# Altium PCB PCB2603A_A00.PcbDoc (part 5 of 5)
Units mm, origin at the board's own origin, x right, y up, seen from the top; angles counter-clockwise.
Board outline 35.56 x 55.88 mm, 8 copper layers (Top Layer, Signal Layer 1, Signal Layer 2, Signal Layer 3, Signal Layer 4, Signal Layer 5, Signal Layer 6, Bottom Layer), stack 1.497 mm thick; 167 components, 113 nets, 4957 pads, 645 vias.
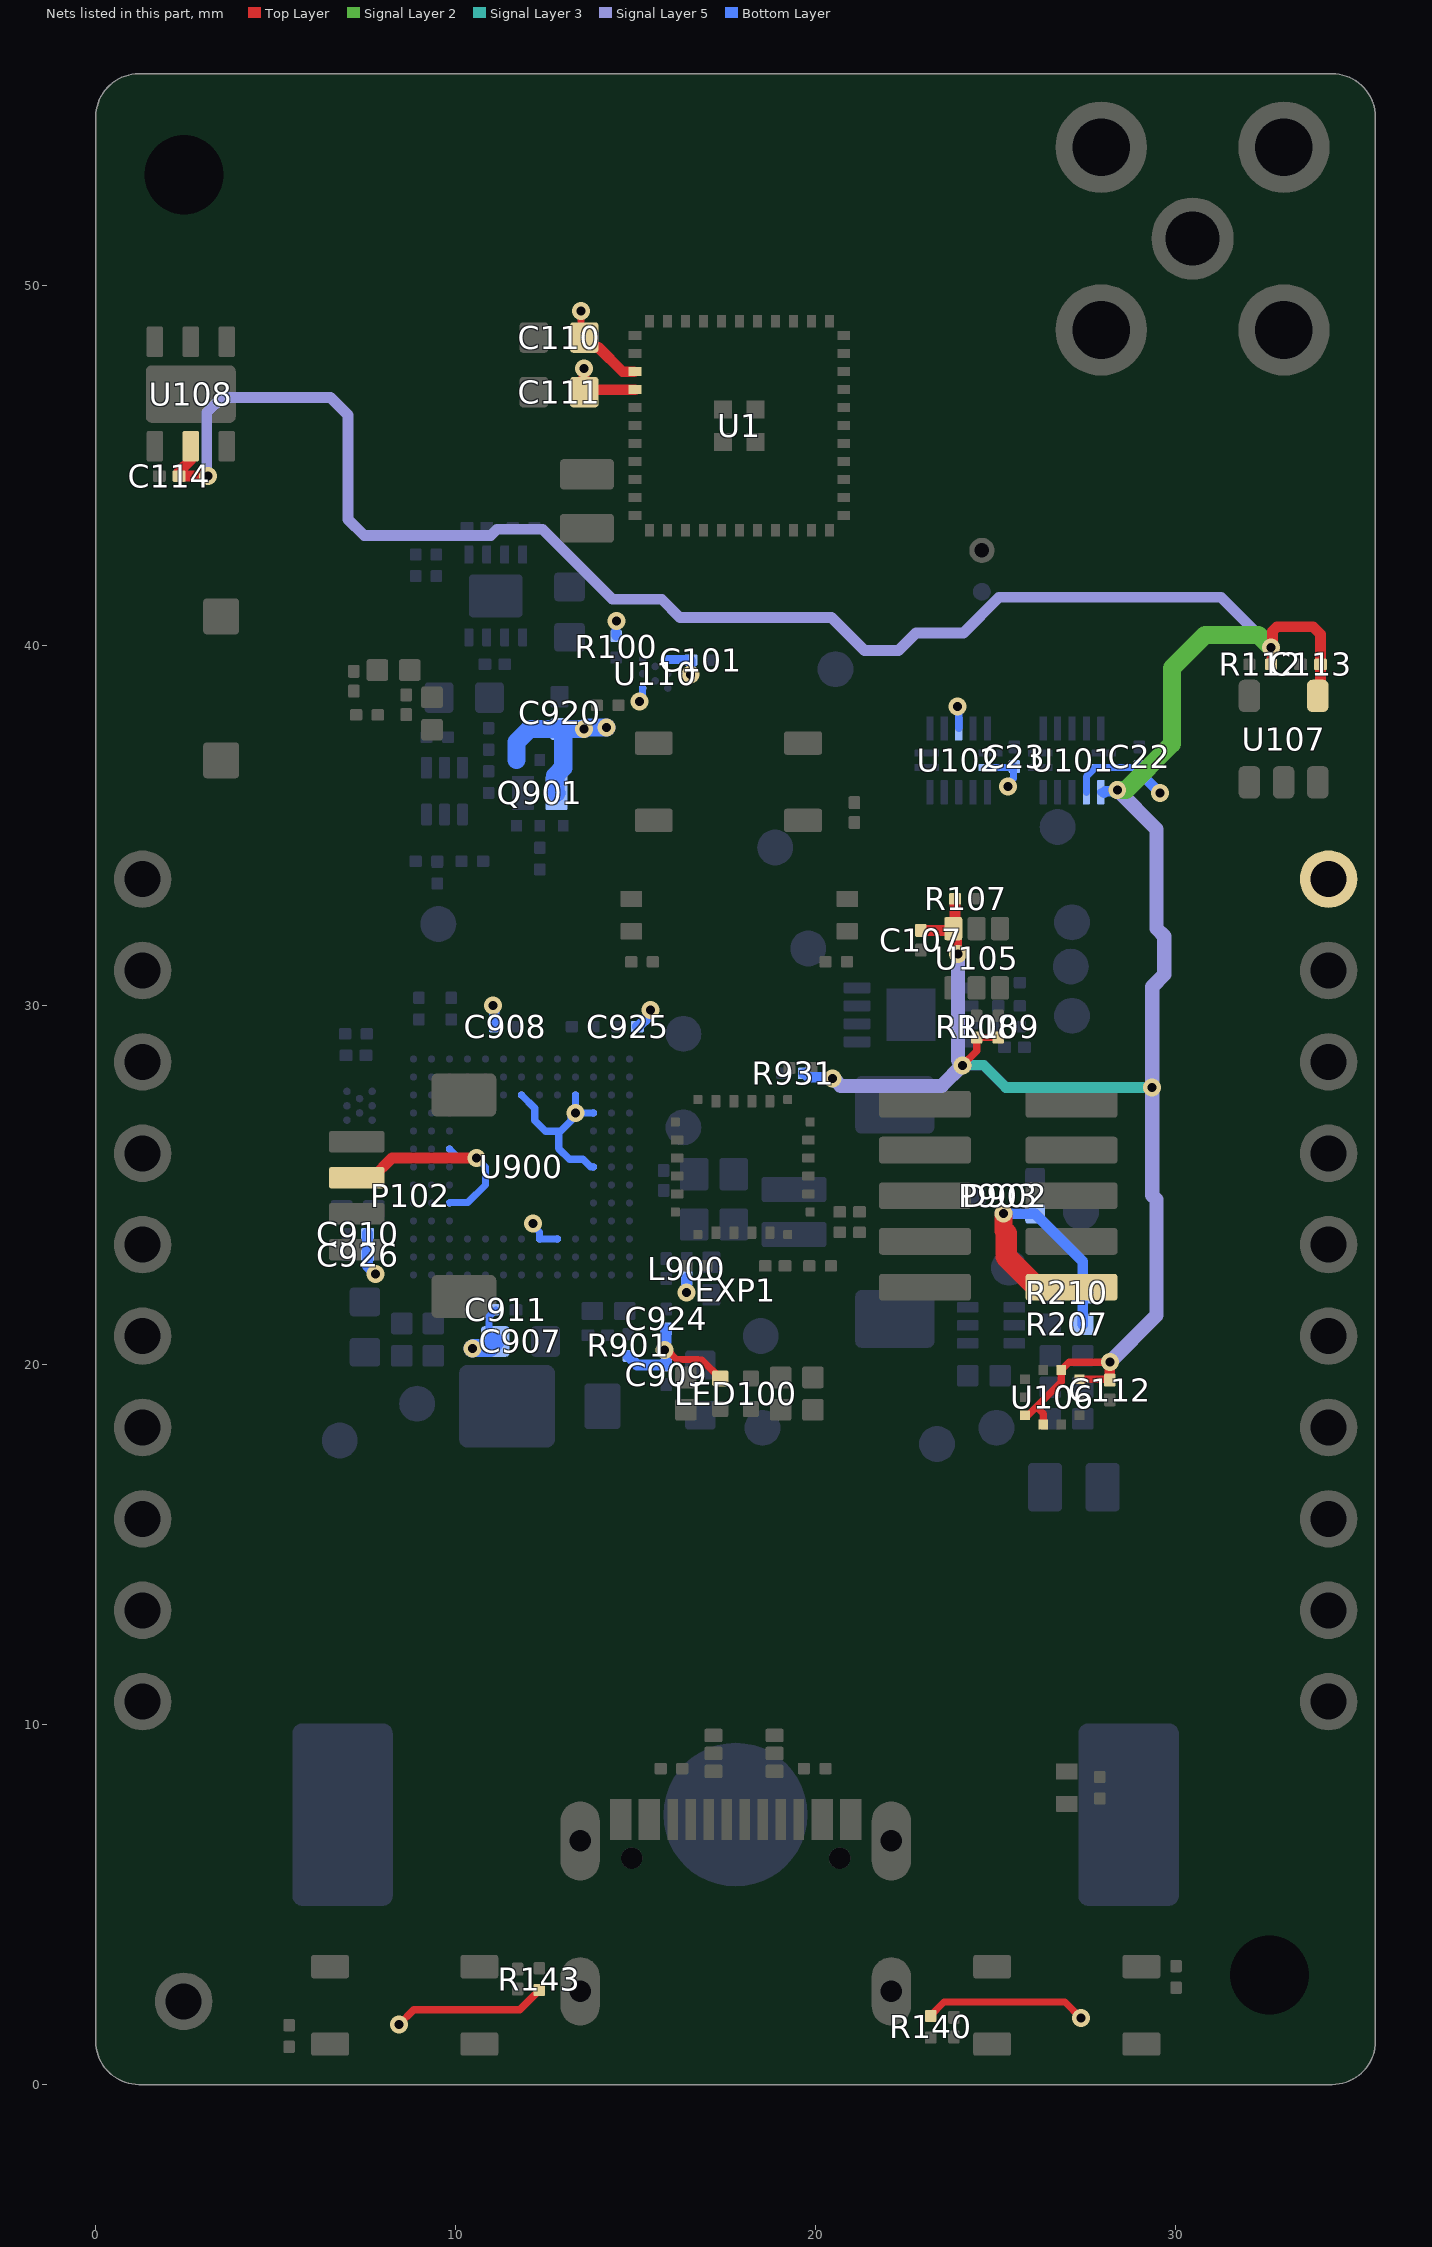
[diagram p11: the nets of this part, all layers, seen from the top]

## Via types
v1: diameter 0.5, hole 0.25, Top Layer to Bottom Layer, tented both sides, 645 vias

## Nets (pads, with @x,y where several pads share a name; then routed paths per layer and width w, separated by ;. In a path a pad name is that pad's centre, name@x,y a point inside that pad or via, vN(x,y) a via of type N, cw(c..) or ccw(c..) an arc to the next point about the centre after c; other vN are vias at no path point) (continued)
VDD_SENSOR: C107.1 C112.1 C113.1 C114.1 R107.1 R108.1 R109.1 R112.1 R931.2 U101.1 U105.6 U106.1 U106.5 U106.6 U106.10 U107.4 U108.5 | length 90.8
  Top Layer w0.2: v1(24.08,28.325) 24.48,28.725 R108.1@24.48,29.1 R109.1@25.08,29.1 ; U106.5@25.823,18.6 25.905,18.6 26.143,18.838 ; U106.6@26.33,18.343 26.33,18.65 26.143,18.838 ; U106.10@27.337,19.6 28.155,19.6 C112.1@28.18,19.575 ; v1(28.18,20.075) 27.048,20.075 U106.1@26.83,19.858 26.83,19.525 26.143,18.838 ; R112.1@32.66,39.465 32.641,39.484 32.641,39.816 32.665,39.839 v1(32.665,39.937)
  Top Layer w0.3: U108.5@2.64,45.3 2.64,45.15 2.315,44.825 C114.1@2.315,44.7 2.318,44.703 2.945,44.703 2.997,44.755 v1@3.051,44.755 ; C107.1@22.93,32.075 23.78,32.075 U105.6@23.83,32.125 ; R107.1@23.88,32.95 23.88,32.175 U105.6@23.83,32.125 ; v1(23.963,31.418) 23.925,31.456 23.925,32.03 U105.6@23.83,32.125 ; C112.1@28.18,19.575 v1(28.18,20.075) ; v1(32.665,39.937) 32.703,39.975 32.703,40.386 32.83,40.512 33.825,40.512 34.035,40.303 C113.1@34.035,39.465 ; U107.4@33.96,38.59 34.035,38.665 C113.1@34.035,39.44
  Signal Layer 2 w0.5: v1(28.387,35.98) 28.625,35.98 29.906,37.261 29.906,39.369 30.825,40.288 32.314,40.288 v1(32.665,39.937)
  Signal Layer 5 w0.3: v1@3.082,44.786 3.082,46.464 3.505,46.887 6.523,46.887 7.011,46.398 7.011,43.495 7.459,43.048 10.978,43.048 11.152,43.221 12.413,43.221 14.359,41.275 15.727,41.275 16.232,40.77 20.449,40.77 21.367,39.852 22.308,39.852 22.797,40.341 24.114,40.341 25.103,41.33 31.272,41.33 v1(32.665,39.937)
  Signal Layer 5 w0.4: v1@20.499,27.933 20.526,27.933 20.708,27.75 23.505,27.75 v1(24.08,28.325) 24.08,28.352 23.963,28.469 v1(23.963,31.418) ; v1(28.18,20.075) 29.479,21.374 29.479,24.594 29.357,24.717 v1(29.357,27.712) 29.357,30.51 29.696,30.849 29.696,31.911 29.479,32.128 29.479,34.888 v1(28.387,35.98)
  Signal Layer 3 w0.3: v1(24.08,28.325) 24.677,28.325 25.289,27.712 v1(29.357,27.712)
  Bottom Layer w0.2: U101.1@27.93,35.915 28.009,35.915 U101.1@28.017,35.907 ; v1@28.294,35.915 28.321,35.942 28.359,35.98 v1(28.387,35.98)
  Bottom Layer w0.3: R931.2@19.68,28.1 19.69,28.09 19.7,28.09 19.8,27.99 20.441,27.99 v1(20.479,27.952) ; U101.1@28.017,35.907 28.052,35.942 28.321,35.942 28.349,35.942 v1(28.387,35.98)
  other v1: 3.12,44.7
VMCU: C22.1 C23.1 C101.1 C110.1 C111.1 C907.1 C908.1 C909.1 C910.1 C911.1 C920.1 C924.1 C925.1 C926.1 D902.2 EXP1.2 L900.1 LED100.1 P102.2 P903.1 Q901.4 Q901.6 Q901.7 R100.2 R140.1 R143.1 R207.2 R210.2 R901.2 U1.25 U1.26 U101.2 U101.14 U102.10 U102.14 U110.A1 U110.E3 U900.C6 U900.C9 U900.G3 U900.H11 U900.J11 U900.K3 U900.L4 U900.L7 | length 54.6
  Top Layer w0.2: v1(8.429,1.669) 8.838,2.078 11.783,2.078 12.325,2.62 R143.1@12.325,2.63 ; C110.1@13.486,48.47 v1(13.486,49.288) ; v1(15.801,20.41) 15.882,20.41 16.141,20.15 16.748,20.15 16.767,20.131 16.849,20.131 LED100.1@17.355,19.625 ; R140.1@23.2,1.904 23.2,1.914 23.576,2.29 26.936,2.29 v1(27.376,1.85) ; v1@23.859,38.262 23.895,38.297 v1(23.952,38.297)
  Top Layer w0.25: v1(16.526,39.189) v1@16.526,39.195
  Top Layer w0.3: P102.2@7.255,25.2 7.68,25.2 8.23,25.75 v1(10.58,25.75) ; v1(13.566,47.684) 13.571,47.679 13.571,47.17 C111.1@13.641,47.1 ; C111.1@13.575,47.032 13.643,47.1 U1.26@14.985,47.1 ; C110.1@13.575,48.55 13.575,48.525 13.825,48.275 13.97,48.275 14.645,47.6 U1.25@14.96,47.6
  Top Layer w0.5: v1(25.23,24.2) 25.23,23.725 25.305,23.65
  Top Layer w0.6: 25.305,23.65 25.305,23 26.075,22.23 27.045,22.23 P903.1@27.115,22.16
  Signal Layer 5 w0.4: v1@10.58,25.723 v1(10.58,25.75) v1@10.607,25.75 ; v1@12.136,23.906 v1(12.155,23.925) v1@12.155,23.898 ; v1@13.311,27.019 v1(13.33,27)
  Bottom Layer w0.2: U900.C9@9.83,24.5 9.84,24.51 10.34,24.51 10.83,25 10.83,25.5 v1(10.58,25.75) 10.08,25.75 U900.C6@9.83,26 ; C907.1@10.925,20.655 10.925,21.345 11.105,21.525 C911.1@11.125,21.525 ; U900.G3@11.83,27.5 12.197,27.133 12.197,26.79 12.495,26.492 12.915,26.492 ; v1(12.155,23.925) 12.155,23.87 12.33,23.695 U900.H11@12.33,23.5 U900.J11@12.83,23.5 ; U900.K3@13.33,27.5 v1(13.33,27) ; U900.L7@13.83,25.5 13.755,25.5 13.544,25.712 13.164,25.712 12.867,26.009 12.867,26.443 12.915,26.492 ; U900.L4@13.83,27 v1(13.33,27) ; v1(15.106,38.442) 15.195,38.53 15.195,38.806 U110.E3@15.197,38.808 ; v1(23.952,38.297) 23.98,38.27 U102.10@23.98,37.685 ; U102.14@24.865,36.6 C23.1@25.505,36.6 ; v1(25.355,36.074) 25.355,36.155 25.505,36.305 C23.1@25.505,36.6 ; C23.1@25.53,36.625 C23.1@25.505,36.6 ; U101.2@27.53,35.915 27.53,36.355 27.775,36.6 28.975,36.6 C22.1@29,36.625 ; 12.915,26.492 13.213,26.79 13.213,26.883 v1(13.33,27)
  Bottom Layer w0.25: R100.2@14.46,40.255 14.46,40.671 v1(14.466,40.677) ; U110.A1@15.897,39.608 16.524,39.608 C101.1@16.544,39.588 16.542,39.587 16.542,39.206 v1(16.526,39.189)
  Bottom Layer w0.3: C910.1@7.555,23.65 C926.1@7.555,23.05 7.555,22.75 v1(7.78,22.525) ; v1(11.044,29.983) 11.075,29.952 11.075,29.41 11.085,29.4 C908.1@11.105,29.4 ; R901.2@14.8,20.25 14.8,20.24 15.04,20 C909.1@15.855,20 15.855,20.33 15.801,20.384 v1(15.801,20.41) 15.839,20.448 15.839,20.63 15.845,20.636 15.845,20.99 C924.1@15.855,21 ; C925.1@15.055,29.4 15.075,29.4 15.374,29.699 15.374,29.823 v1(15.412,29.861) ; v1(16.421,22.012) 16.426,22.016 16.426,22.401 L900.1@16.43,22.405 ; v1(25.23,24.2) D902.2@26.105,24.2 27.43,22.875 R210.2@27.43,22 27.43,21.95 R207.2@27.43,21.125 ; C22.1@29,36.625 29.01,36.615 29.01,36.457 v1(29.58,35.887)
  Bottom Layer w0.5: v1(10.474,20.458) 10.491,20.475 10.95,20.475 11.1,20.625 C907.1@11.1,20.65 ; v1(13.565,37.67) 13.603,37.708 v1(14.193,37.708)
  Bottom Layer w0.508: Q901.4@11.69,36.808 11.69,37.313 12.047,37.67 C920.1@12.89,37.67 v1(13.565,37.67) ; Q901.7@12.806,35.895 12.765,35.936 12.765,36.37 12.99,36.595 Q901.6@12.99,36.808 12.99,37.528 C920.1@12.89,37.628
pads on no net: c.7 c.9 LOGO_SEGGER.1 M901.1 M902.1 P102.5 P102.6 P900.1 P900.2 P900.A8 P900.B8 U1.18 U1.24 U104.1 U104.2 U104.3 U104.4 U104.5 U104.6 U104.7 U104.14 U104.15 U104.16 U104.17 U104.19 U104.20 U104.21 U105.4 U108.3 U108.4 U108.7 U110.C1 U900.B4 U900.B5 U900.B6 U900.B7 U900.B8 U900.B9 U900.B11 U900.C4 U900.C7 U900.D2 U900.D13 U900.E2 U900.E11 U900.E12 U900.E13 U900.F1 U900.F2 U900.F3 U900.F11 U900.F12 U900.G1 U900.G2 U900.G12 U900.H1 U900.H2 U900.J1 U900.J2 U900.K1 U900.K2 U900.K13 U900.L3 U900.L11 U900.L12 U900.L13 U900.M2 U900.M3 U900.M4 U900.M5 U900.M6 U900.M12 U900.M13 U900.N3 U900.N4 U900.N5 U900.N6 U900.N7 U900.N13 U901.C1 U902.8 U903.9
copper on no net:
  other v1: 31.289,4.77

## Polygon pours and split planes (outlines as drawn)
GND on Signal Layer 1 "GND_L02" (solid, remove dead copper, pour order 1): -0.015,0 -0.015,55.88 35.56,55.88 35.56,0
GND on Signal Layer 4 "GND_L05" (solid, remove dead copper, pour order 11): -0.015,0 -0.015,55.88 35.56,55.88 35.56,0
GND on Signal Layer 5 "GND_L06" (solid, remove dead copper, pour order 7): -0.015,0 -0.015,55.88 35.56,55.88 35.56,0
GND on Signal Layer 2 "GND_L03" (solid, remove dead copper, pour order 10): -0.015,0 -0.015,55.88 35.56,55.88 35.56,0
GND on Signal Layer 3 "GND_L04" (solid, remove dead copper, pour order 6): -0.015,0 -0.015,55.88 35.56,55.88 35.56,0
GND on Bottom Layer "GND_L08" (solid, remove dead copper, pour order 8): -0.015,0 -0.015,55.88 35.56,55.88 35.56,0
GND on Top Layer "CC" (solid, remove dead copper, pour order 0): -0.015,0 -0.015,55.88 35.56,55.88 35.56,0
VMCU on Signal Layer 6 "VMCU_L07" (solid, remove dead copper, pour order 9): -0.015,0 -0.015,55.88 35.56,55.88 35.56,0

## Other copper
Top Layer:
  pour cut-out: 20.177,26.014 20.197,26.034 20.657,26.034 20.657,25.867 20.517,25.727 20.457,25.787 20.184,25.787
  pour cut-out: 21.807,25.593 21.807,25.085 21.82,25.073 24.153,25.073 24.217,25.137 24.217,25.548 24.185,25.58
  pour cut-out: 12.233,42.705 15.166,42.705 15.166,44.801 14.723,45.245 12.257,45.245
  pour cut-out: 25.919,26.301 25.919,25.669 25.944,25.645 25.944,25.186 28.335,25.186 28.335,26.202 28.193,26.344
  pour cut-out: 6.598,35.403 6.598,42.431 0.153,42.431 0.153,35.403
Signal Layer 2:
  pour cut-out: 5.477,21.481 5.778,21.481 5.778,21.48 5.778,21.646 5.727,21.698 5.487,21.698 5.484,21.695
  pour cut-out: 16.076,49.381 16.164,49.469 17.817,49.469 17.817,50.075 17.77,50.123 16.054,50.123 16.043,50.112 16.091,50.064 16.091,49.414
  pour cut-out: 14.637,36.387 14.669,36.355 15.338,36.355 15.338,37.666 15.295,37.709 14.664,37.709
Bottom Layer:
  pour cut-out: 17.193,19.118 17.193,19.489 17.197,19.493 16.788,19.493 16.724,19.429 16.724,19.11
  region net N16784657: 8.357,4.811 8.357,11.509 5.295,11.509 5.295,4.811
  pour cut-out: 25.451,24.894 25.451,24.518 25.447,24.513 25.626,24.513 25.626,24.85 25.657,24.881
  pour cut-out: 25.5,20.027 25.5,19.68 25.563,19.617 25.709,19.617 25.757,19.666 25.743,19.68 25.743,20.013
  pour cut-out: 12.44,39.27 12.665,39.27 12.665,38.77 12.44,38.77
  pour cut-out: 8.364,22.1 15.28,22.1 15.28,29.114 8.415,29.114
  pour cut-out: 6.98,20.95 6.98,21.85 7.93,21.85 7.93,20.95
Multi-Layer:
  pour cut-out: -0.119,43.751 -0.119,50.001 cw(c0.381,50.001) 0.381,50.501 4.881,50.501 cw(c4.881,50.001) 5.381,50.001 5.381,43.751 cw(c4.881,43.751) 4.881,43.251 0.381,43.251 cw(c0.381,43.751)

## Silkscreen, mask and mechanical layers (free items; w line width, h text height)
Top Solder:
  lines w0.8: -2.398,4.25 -2.398,1.189 ccw(c1.191,1.189) 1.191,-2.4 34.371,-2.4 ccw(c34.371,1.189) 37.96,1.189 37.96,4.25 ; -2.398,51.63 -2.398,54.795 cw(c1.139,54.743) 1.191,58.28 34.474,58.28 ; -2.397,4.25 -2.398,12.25 ; -2.398,16.75 -2.398,47.13 ; 0,54.808 0,1.19 ccw(c1.19,1.191) 1.191,0.001 ; 0,54.81 cw(c1.072,54.808) 1.074,55.88 ; 1.072,55.88 34.47,55.88 ; 1.191,0 34.369,0 ; 34.371,0 ccw(c34.371,1.189) 35.56,1.19 35.56,54.79 ; 34.374,58.262 cw(c34.474,54.778) 37.957,54.878 ; 34.468,55.88 cw(c34.47,54.79) 35.56,54.792 ; 37.959,54.778 37.959,51.63 37.96,51.63 ; 37.96,12.25 37.961,4.25 ; 37.96,16.75 37.96,47.13 ; 0,1.2 ccw(c1.2,1.2) 1.2,0 ; 0,1.2 ccw(c1.2,1.2) 1.2,0 ; 0,1.2 0,54.68 ; 0,1.2 0,54.68 ; 0,54.68 cw(c1.2,54.68) 1.2,55.88 ; 0,54.68 cw(c1.2,54.68) 1.2,55.88 ; 1.2,0 34.36,0 ; 1.2,0 34.36,0 ; 1.2,55.88 34.36,55.88 ; 1.2,55.88 34.36,55.88 ; 34.36,0 ccw(c34.36,1.2) 35.56,1.2 cw(c34.36,1.2) 34.36,0 ; 34.36,55.88 cw(c34.36,54.68) 35.56,54.68 ccw(c34.36,54.68) 34.36,55.88 ; 35.561,1.2 35.561,54.68 35.561,1.2
Bottom Solder:
  lines w0.8: -2.398,1.189 ccw(c1.191,1.189) 1.191,-2.4 ; -2.398,16.75 -2.398,47.13 ; -2.398,51.63 -2.397,51.63 -2.397,54.709 ; -2.398,54.795 cw(c1.139,54.743) 1.191,58.28 ; -2.398,1.189 -2.398,4.25 -2.398,12.25 ; 0,44.4 0,1.189 ccw(c1.19,1.19) 1.191,0 ; 0.001,54.807 0.001,1.19 ccw(c1.191,1.191) 1.192,0.001 ; 0.001,54.808 cw(c1.074,54.807) 1.076,55.88 ; 1.074,55.88 34.469,55.88 ; 1.192,-2.4 34.372,-2.4 ; 1.192,0 34.37,0 ; 1.192,58.28 34.371,58.28 cw(c34.471,54.791) 37.96,54.891 ; 34.371,-2.4 ccw(c34.371,1.189) 37.96,1.189 ; 34.371,0 ccw(c34.371,1.189) 35.56,1.189 35.56,44.4 ; 34.372,0 ccw(c34.372,1.189) 35.561,1.19 35.561,54.788 ; 34.467,55.88 cw(c34.469,54.788) 35.561,54.79 ; 37.96,12.25 37.961,4.25 37.961,1.189 ; 37.96,16.75 37.96,47.13 ; 37.96,51.63 37.96,54.984 ; 0,1.2 ccw(c1.2,1.2) 1.2,0 ; 0,1.2 ccw(c1.2,1.2) 1.2,0 ; 0,1.2 0,54.68 ; 0,1.2 0,54.68 ; 0,54.68 cw(c1.2,54.68) 1.2,55.88 ; 0,54.68 cw(c1.2,54.68) 1.2,55.88 ; 1.2,0 34.36,0 ; 1.2,0 34.36,0 ; 1.2,55.88 34.36,55.88 ; 1.2,55.88 34.36,55.88 ; 34.36,0 ccw(c34.36,1.2) 35.56,1.2 cw(c34.36,1.2) 34.36,0 ; 34.36,55.88 cw(c34.36,54.68) 35.56,54.68 ccw(c34.36,54.68) 34.36,55.88 ; 35.561,1.2 35.561,54.68 35.561,1.2
BOARD OUTLINE 1:
  drawing of 315 lines, arcs and shapes, not listed
  text "Milling 0.8 mm (2 pcs)" at 6.177,42.873 h0.9 r90
Mechanical 15:
  lines w0.1: 2.08,0 3.08,0 ; 2.58,-0.5 2.58,0.5
Top EXT_SILKP 21/EXT_SILKS 22:
  text "ZGM230S" at 13.818,40.388 h2
  text "RESET" at 15.745,38.164 h1.27
  text "2" at 31.94,33.06 h1.5
  text "1" at 3.083,33 h1.5
  text "LED1" at 11.479,32.092 h1.27
  text "LED0" at 17.328,32.099 h1.27
  text "4" at 31.94,30.512 h1.5
  text "3" at 3.083,30.42 h1.5
  text "6" at 31.94,27.972 h1.5
  text "5" at 3.083,27.845 h1.5
  text "8" at 31.94,25.435 h1.5
  text "7" at 3.083,25.295 h1.5
  text "10" at 31.385,22.935 h1.5
  text "9" at 3.083,22.82 h1.5
  text "2" at 22.54,20.792 h1.27
  text "1" at 26.73,20.792 h1.27
  text "12" at 31.385,20.41 h1.5
  text "RGB LED" at 15.364,20.294 h1.27
  text "11" at 2.808,20.22 h1.5
  text "14" at 31.385,17.835 h1.5
  text "13" at 2.783,17.645 h1.5
  text "16" at 31.385,15.31 h1.5
  text "15" at 2.783,15.145 h1.5
  text "18" at 31.385,12.76 h1.5
  text "17" at 2.783,12.595 h1.5
  text "20" at 31.385,10.26 h1.5
  text "19" at 2.783,10.095 h1.5
  text "BTN0" at 25.603,3.849 h1.27
  text "BTN1" at 7.281,3.842 h1.27
Bottom EXT_SILKP 21/EXT_SILKS 22:
  circle w0.152: c2.443,2.313 r0.966
  lines w0.152: 13.34,52.055 13.34,51.055 14.34,51.055 ; 13.34,54.105 13.34,55.105 14.34,55.105 ; 22.84,51.055 23.84,51.055 23.84,52.055 ; 22.84,55.105 23.84,55.105 23.84,54.105
  text "PCB2603A Rev A00" at 34.093,34.87 h1.5 r270
Mechanical 26:
  lines w0.2: -117.029,-49.807 -112.029,-49.807 ; -117.029,-2.807 -112.029,-2.807 ; -117.017,44.193 -112.029,44.193 ; -45.821,-96.838 -45.821,-91.838 ; -45.821,88.162 -45.821,93.162 ; 25.479,-96.838 25.479,-91.838 ; 25.479,88.162 25.479,93.162 ; 96.679,-96.838 96.679,-91.838 ; 96.679,88.162 96.679,93.162 ; 162.971,-49.807 167.971,-49.807 ; 162.971,-2.807 167.971,-2.807 ; 162.971,44.193 167.959,44.193 ; -117.017,-96.838 -117.017,93.154 167.971,93.154 167.971,-96.838 -117.017,-96.838 ; -112.029,-91.838 -112.029,88.162 162.971,88.162 162.971,-91.838 -112.029,-91.838
  text "1" at -84.129,89.733 h1.52
  text "2" at -11.821,89.733 h1.52
  text "3" at 60.779,89.733 h1.52
  text "4" at 131.579,89.733 h1.52
  text "D" at 164.969,70.593 h1.52
  text "D" at -115.142,69.388 h1.52
  text "C" at -115.142,21.893 h1.52
  text "C" at 164.842,21.893 h1.52
  text "B" at -115.142,-25.707 h1.52
  text "B" at 164.842,-25.707 h1.52
  text "A" at -115.142,-73.207 h1.52
  text "A" at 164.842,-73.207 h1.52
  text "1" at -82.909,-95.28 h1.52
  text "2" at -11.821,-95.28 h1.52
  text "3" at 60.479,-95.28 h1.52
  text "4" at 131.179,-95.28 h1.52
Mechanical 27:
  circle w0.152: c78.907,-70.307 r0.762
  circle w0.152: c78.907,-70.307 r1.778
  circle w0.254: c46.923,-84.764 r2.962
  lines w0.152: 67.909,-70.307 75.275,-70.307 ; 76.621,-70.307 81.193,-70.307 ; 68.671,-71.069 74.488,-72.085 74.513,-68.529 68.671,-69.545 68.671,-71.069
  lines w0.2: 42.874,-91.698 42.874,-64.838 82.888,-64.838 ; 42.874,-77.474 162.839,-77.474 ; 42.888,-73.838 82.888,-73.838 ; 63.169,-91.647 63.169,-77.55 ; 63.169,-73.791 63.169,-64.875 ; 142.888,-77.448 142.888,-73.838 ; 152.888,-73.838 152.888,-64.838 ; 162.888,-73.838 82.888,-73.838 ; 162.888,-64.838 82.888,-64.838 ; 82.888,-73.838 82.888,-64.838
  text "SIZE" at 44.888,-66.838 h1.52
  text "DOC NO" at 84.888,-66.838 h1.52
  text "REV" at 154.888,-66.838 h1.52
  text "PROJECTION" at 64.185,-67.187 h1.52
  text "A00" at 154.609,-71.759 h2.54
  text "BRD2603A" at 85.21,-72.2 h2.54
  text "A4" at 47.538,-72.212 h2.54
  text "REF" at 44.888,-75.838 h1.52
  text "SHEET" at 143.888,-75.838 h1.52
  text "1 of 2" at 153.73,-76.875 h1.52
  text "This drawing is confidential and is supplied on the express" at 63.652,-80.446 h1.52
  text "condition that it shall not be loaned, copied or disclosed to any" at 63.652,-82.986 h1.52
  text "other person or used for any purpose without the written consent of" at 63.652,-85.526 h1.52
  text "C" at 46.329,-85.78 h2.03
  text "2021" at 51.409,-85.932 h2.54
  text "SILICON LABS" at 64.083,-89.818 h2.54
Mechanical 28:
  lines w0.2: -117.029,-49.807 -112.029,-49.807 ; -117.029,-2.807 -112.029,-2.807 ; -117.017,44.193 -112.029,44.193 ; 162.971,-49.807 167.971,-49.807 ; 162.971,-2.807 167.971,-2.807 ; 162.971,44.193 167.971,44.193
  lines w0.203: -112.054,-91.838 -112.054,88.162 ; -112.029,-91.838 162.971,-91.838 162.971,88.162 -112.029,88.162 ; -45.821,-96.838 -45.821,-91.838 ; -45.821,88.162 -45.821,93.162 ; 25.479,-96.838 25.479,-91.838 ; 25.479,88.162 25.479,93.162 ; 96.679,-96.838 96.679,-91.838 ; 96.679,88.162 96.679,93.162 ; -117.017,-96.838 167.971,-96.838 167.971,93.154 -117.017,93.154 -117.017,-96.838
  text "4" at -83.113,89.733 h1.52
  text "3" at -10.805,89.733 h1.52
  text "2" at 61.795,89.733 h1.52
  text "1" at 132.595,89.733 h1.52
  text "D" at 165.985,70.593 h1.52
  text "D" at -114.126,69.388 h1.52
  text "C" at -114.126,21.893 h1.52
  text "C" at 165.985,20.293 h1.52
  text "B" at -114.126,-25.707 h1.52
  text "B" at 165.985,-26.807 h1.52
  text "A" at -114.126,-73.207 h1.52
  text "A" at 165.858,-73.207 h1.52
  text "4" at -81.893,-95.28 h1.52
  text "3" at -10.805,-95.28 h1.52
  text "2" at 61.342,-95.28 h1.52
  text "1" at 132.195,-95.28 h1.52
Mechanical 29:
  circle w0.152: c-27.951,-70.371 r0.762
  circle w0.152: c-27.951,-70.371 r1.778
  circle w0.254: c4.034,-84.828 r2.962
  lines w0.152: -30.237,-70.371 -25.665,-70.371 ; -24.319,-70.371 -16.953,-70.371 ; -23.557,-68.593 -23.531,-72.149 -17.715,-71.133 -17.715,-69.609 -23.557,-68.593
  lines w0.2: -111.932,-73.902 -31.932,-73.902 ; -111.932,-64.902 -31.932,-64.902 ; -111.882,-77.538 8.082,-77.538 ; -101.932,-73.902 -101.932,-64.902 ; -91.932,-77.513 -91.932,-73.902 ; -12.213,-91.711 -12.213,-77.614 ; -12.213,-73.855 -12.213,-64.94 ; 8.068,-73.902 -31.932,-73.902 ; 8.068,-64.902 -31.932,-64.902 ; 8.082,-91.762 8.082,-64.838 ; -31.932,-73.902 -31.932,-64.902
  text "REV" at -103.932,-66.902 h1.52
  text "DOC NO" at -33.932,-66.902 h1.52
  text "SIZE" at 6.068,-66.902 h1.52
  text "PROJECTION" at -13.229,-67.251 h1.52
  text "A00" at -103.653,-71.823 h2.54
  text "BRD2603A" at -36.432,-72.276 h2.54
  text "A4" at 3.418,-72.276 h2.54
  text "SHEET" at -92.932,-75.902 h1.52
  text "REF" at 6.068,-75.902 h1.52
  text "2 of 2" at -102.62,-76.875 h1.52
  text "This drawing is confidential and is supplied on the express" at -12.695,-80.51 h1.52
  text "condition that it shall not be loaned, copied or disclosed to any" at -12.695,-83.05 h1.52
  text "other person or used for any purpose without the written consent of" at -12.695,-85.59 h1.52
  text "C" at 4.628,-85.844 h2.03
  text "2021" at -0.452,-85.996 h2.54
  text "SILICON LABS" at -13.127,-89.882 h2.54
Mechanical 30:
  lines w0.2: 42.874,-64.838 42.874,-43.998 162.874,-43.998 ; 42.874,-60.902 82.874,-60.902 ; 42.874,-56.902 82.874,-56.902 162.874,-56.903 ; 42.874,-52.902 82.874,-52.902 ; 82.874,-48.902 162.874,-48.902 ; 82.881,-64.838 82.881,-43.998
  text "CUSTOMER" at 83.983,-45.915 h1.27
  text "PROJECT NO" at 44.359,-46.931 h1.52
  text "SILICON LABS" at 101.763,-47.439 h2.03
  text "DRAWING TITLE" at 84.212,-50.843 h1.52
  text "BRD2603A" at 45.505,-51.25 h3.3
  text "DATE" at 44.359,-55.059 h1.52
  text "ZGM230S Dev Kit" at 87.387,-55.106 h2.03
  text ".Print_Date" at 62.647,-56.075 h1.52
  text "SHEET NAME" at 84.008,-58.996 h1.52
  text "DRAWN" at 44.359,-59.123 h1.52
  text "CHECK" at 44.359,-63.187 h1.52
